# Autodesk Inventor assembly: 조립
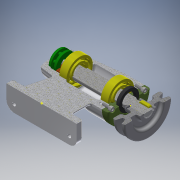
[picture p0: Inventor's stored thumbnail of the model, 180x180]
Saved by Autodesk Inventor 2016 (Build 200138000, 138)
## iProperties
Created: 2018-09
Part Number: 조립
Document SubType Name: Assembly
Designer: CAMTIC
Author: CAMTIC
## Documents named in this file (12)
- C:\Users\CAMTIC\Desktop\480907V1026\답안조립품.iam
- C:\Users\CAMTIC\Desktop\480907V1026\본체.ipt
- C:\Users\CAMTIC\Desktop\480907V1026\V벨트풀리.ipt
- C:\Users\CAMTIC\Desktop\480907V1026\멈춤나사 M3.ipt
- C:\Users\CAMTIC\Desktop\480907V1026\베어링 6004.ipt
- C:\Users\CAMTIC\Desktop\480907V1026\베어링 51202.ipt
- C:\Users\CAMTIC\Desktop\480907V1026\볼트 M4.ipt
- C:\Users\CAMTIC\Desktop\480907V1026\어댑터슬리브.ipt
- C:\Users\CAMTIC\Desktop\480907V1026\오일 실.ipt
- C:\Users\CAMTIC\Desktop\480907V1026\축.ipt
- C:\Users\CAMTIC\Desktop\480907V1026\커버.ipt
- C:\Users\CAMTIC\Desktop\480907V1026\키 5 x 5 x 16.ipt
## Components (1 placed, 1 different names)
1. V벨트풀리:1
